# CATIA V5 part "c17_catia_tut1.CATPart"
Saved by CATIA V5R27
Part number: Part1
Bounding box of the stored display mesh (mm): x 0 to 100, y -49.99 to 49.99, z 0 to 49.98
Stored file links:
  E:\_Deepak\2016_Deepak\CATIA\CATIA V5-6R2016_Deepak\Resources\Tutorial Files\Tutorials\c18_catia_v5_6r2016_tut\c18_catia_tut1.CATPart
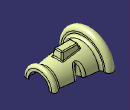
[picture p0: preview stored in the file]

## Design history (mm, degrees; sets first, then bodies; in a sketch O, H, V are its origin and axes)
Body1 (main body)
  Sketch1 on xy-plane, origin (0, 0, 0), H (1, 0, 0), V (0, 1, 0)
    point P1 (0, 30)
    line L1 (0, 30) -> (0, 42.5)
    arc A1 centre (7.5, 42.5) radius 7.5 from (0, 42.5) to (15, 42.5) cw
    point P3 (7.5, 42.5)
    line L2 (15, 42.5) -> (15, 35)
    point P5 (15, 35)
    line L3 (15, 35) -> (90.101, 24)
    point P6 (90.101, 24)
    arc A2 centre (95, 25) radius 5 from (90.101, 24) to (100, 25) cw
    point P7 (95, 25)
    line L4 (100, 25) -> (100, 20)
    point P9 (100, 20)
    axis line L5 (0, 0) -> (130.0291, 0)
    radius A1 = 7.5
    distance L1 L4 = 100
    radius A2 = 5
    radius about axis P1 L5 = 30
    radius about axis P3 L5 = 42.5
    radius about axis P5 L5 = 35
    radius about axis P9 L5 = 20
    radius about axis P7 L5 = 25
    radius about axis P6 L5 = 24
    coincidence: P1 V
    tangency: A1 L1, L2 A1, L4 A2
    vertical: L1 V, L2 V, L4 V
    horizontal: L5 H
  Revol1: Element1 Sketch1, Angle1 180
  Sketch2 on xy-plane, origin (0, 0, 0), H (1, 0, 0), V (0, 1, 0)
    point P1 (50, 29.8736)
    ellipse A1 centre (50, 29.8736) semi-axes 10, 5 rotation 90
    reference projected line E1 (90.101, 24) -> (15, 35) from Sketch1.L3
    reference projected point E2 (100, 20) from Sketch1.P9
    ellipse A2 centre (50, -29.8736) semi-axes 10, 5 rotation 270
    "Radius" A1 = 10
    "Radius" A1 = 5
    distance P1 E2 H = 50
    vertical: A1 V
    coincidence: P1 E1
    symmetry: A1 A2 H
  Extrude1: Lim1 40, Lim2 0, Direction xy-plane, Element1 Sketch2
  Trim1: Trimmed (Revol1; Extrude1)
  Fillet1: radius 5, on edge [face of Revol1 from Sketch1.L3 | face of Extrude1 from Sketch2.A2]; edge [face of Revol1 from Sketch1.L3 | face of Extrude1 from Sketch2.A1]
  Plane1: type Offset, RefPlane xy-plane, Offset 40
  Sketch3 on Plane1, origin (0, 0, 40), H (1, 0, 0), V (0, 1, 0)
    line L1 (30, 10) -> (65, 10)
    line L2 (65, 10) -> (65, -10)
    line L3 (65, -10) -> (30, -10)
    line L4 (30, -10) -> (30, 10)
    reference projected line E1 (100, 25) -> (100, -25) from edge [face of Revol1 from Sketch1.L4 | face of Revol1 from Sketch1.A2]
    distance L2 E1 = 35
    length L1 = 35
    length L2 = 20
    horizontal: L1 H, L3 H
    vertical: L2 V, L4 V
    symmetry: L1 L3 H
  Project1: ToProject Sketch3, Support Fillet1, Direction xy-plane
  Sketch4 on Plane1, origin (0, 0, 40), H (1, 0, 0), V (0, 1, 0)
    line L1 (32.5, 7.5) -> (62.5, 7.5)
    line L2 (62.5, 7.5) -> (62.5, -7.5)
    line L3 (62.5, -7.5) -> (32.5, -7.5)
    line L4 (32.5, -7.5) -> (32.5, 7.5)
    reference projected line E1 (100, 25) -> (100, -25) from edge [face of Revol1 from Sketch1.L4 | face of Revol1 from Sketch1.A2]
    distance L2 E1 = 37.5
    length L1 = 30
    length L2 = 15
    horizontal: L1 H, L3 H
    vertical: L2 V, L4 V
    symmetry: L3 L1 H
  Loft1: Sections (Project1; Sketch4), SectionCouplingPoints ({coupling CouplingPoints (vertex [face of Project1 | face of Project1]; vertex [element of Sketch4 | element of Sketch4])}; {coupling CouplingPoints (vertex [face of Project1 | face of Project1]; vertex [element of Sketch4 | element of Sketch4])}; {coupling CouplingPoints (vertex [face of Project1 | face of Project1]; vertex [element of Sketch4 | element of Sketch4])})
  Trim2: Trimmed (Loft1; Fillet1)
  Fill1: Boundary (edge of Loft1; edge of Loft1; edge of Loft1; edge of Loft1)
  Join1: Elements (Trim2; Fill1)
  Fillet2: radius 5, on edge [face of Revol1 from Sketch1.L3 | face of Revol1 from Sketch1.L2]; edge [face of Revol1 from Sketch1.A2 | face of Revol1 from Sketch1.L3]
  Fillet3: radius 2, on face of Fill1; edge [face of Loft1 | face of Loft1]; face of Loft1 (x4)
  Set1
    ThickSurface1: BotOffset 0, Surface Fillet3, TopOffset 1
